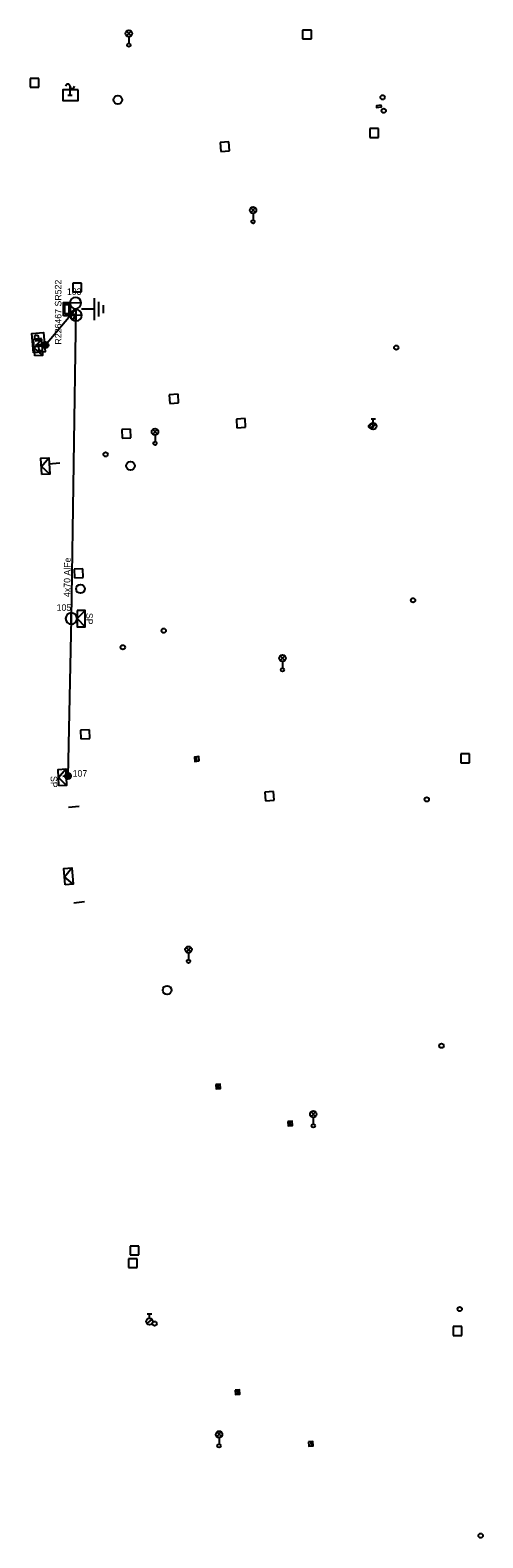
# Model space of a CAD drawing. Extents: x -544660 to -541587, y -1198996 to -1195866.
# Drawn here: x -542658.7 to -542606.9, y -1198470.6 to -1198298.2 of the extents above; entities that cross this region are included whole.
import ezdxf

# ---------------------------------------------------------------- set-up
doc = ezdxf.new("R2010")
doc.units = 0
for name, color, linetype in [('CIZÍ_NADZEM', 7, 'Continuous'), ('ELE_EON', 7, 'Continuous'), ('ELE_EON_POPIS', 7, 'Continuous'), ('SDEL_EON', 7, 'Continuous')]:
    doc.layers.add(name, color=color, linetype=linetype)

msp = doc.modelspace()

# ---------------------------------------------------------------- linework, layer by layer
at = {"layer": 'CIZÍ_NADZEM'}
for p, q in [((-542647.7, -1198298.88), (-542647.18, -1198298.35)), ((-542647.17, -1198298.88), (-542647.7, -1198298.35)), ((-542627.56, -1198298.25), (-542627.56, -1198299.25)), ((-542626.56, -1198298.25), (-542627.56, -1198298.25)), ((-542626.56, -1198299.25), (-542626.56, -1198298.25)), ((-542647.44, -1198298.99), (-542647.44, -1198299.74)), ((-542627.56, -1198299.25), (-542626.56, -1198299.25)), ((-542658.72, -1198303.76), (-542658.72, -1198304.76)), ((-542657.72, -1198303.76), (-542658.72, -1198303.76)), ((-542658.72, -1198304.76), (-542657.72, -1198304.76)), ((-542657.72, -1198304.76), (-542657.72, -1198303.76)), ((-542654.16, -1198305.66), (-542654.16, -1198304.66)), ((-542654.41, -1198305.66), (-542653.91, -1198305.66)), ((-542619.89, -1198309.5), (-542619.89, -1198310.5)), ((-542618.89, -1198309.5), (-542619.89, -1198309.5)), ((-542618.89, -1198310.5), (-542618.89, -1198309.5)), ((-542635.99, -1198311.02), (-542636.99, -1198311.1)), ((-542636.99, -1198311.1), (-542636.91, -1198312.1)), ((-542636.91, -1198312.1), (-542635.91, -1198312.02)), ((-542635.91, -1198312.02), (-542635.99, -1198311.02)), ((-542619.89, -1198310.5), (-542618.89, -1198310.5)), ((-542633.49, -1198319.08), (-542632.97, -1198318.55)), ((-542632.96, -1198319.07), (-542633.49, -1198318.55)), ((-542633.23, -1198319.19), (-542633.23, -1198319.94)), ((-542653.84, -1198327.15), (-542653.84, -1198328.15)), ((-542652.84, -1198327.15), (-542653.84, -1198327.15)), ((-542652.84, -1198328.15), (-542652.84, -1198327.15)), ((-542653.84, -1198328.15), (-542652.84, -1198328.15)), ((-542641.81, -1198339.85), (-542642.81, -1198339.91)), ((-542642.81, -1198339.91), (-542642.75, -1198340.91)), ((-542642.75, -1198340.91), (-542641.75, -1198340.85)), ((-542641.75, -1198340.85), (-542641.81, -1198339.85)), ((-542634.14, -1198342.63), (-542635.14, -1198342.69)), ((-542635.14, -1198342.69), (-542635.08, -1198343.69)), ((-542634.08, -1198343.63), (-542634.14, -1198342.63)), ((-542619.74, -1198342.65), (-542619.24, -1198342.65)), ((-542619.49, -1198343.15), (-542619.49, -1198342.65)), ((-542647.25, -1198343.83), (-542648.25, -1198343.89)), ((-542648.25, -1198343.89), (-542648.19, -1198344.89)), ((-542648.19, -1198344.89), (-542647.19, -1198344.83)), ((-542647.19, -1198344.83), (-542647.25, -1198343.83)), ((-542644.7, -1198344.41), (-542644.18, -1198343.88)), ((-542644.17, -1198344.41), (-542644.7, -1198343.88)), ((-542644.44, -1198344.52), (-542644.44, -1198345.27)), ((-542635.08, -1198343.69), (-542634.08, -1198343.63)), ((-542619.78, -1198343.75), (-542619.19, -1198343.29)), ((-542652.7, -1198359.81), (-542653.7, -1198359.85)), ((-542653.7, -1198359.85), (-542653.66, -1198360.85)), ((-542652.66, -1198360.81), (-542652.7, -1198359.81)), ((-542653.66, -1198360.85), (-542652.66, -1198360.81)), ((-542630.13, -1198370.29), (-542629.61, -1198369.76)), ((-542629.6, -1198370.28), (-542630.13, -1198369.76)), ((-542629.87, -1198370.4), (-542629.87, -1198371.15)), ((-542651.95, -1198378.2), (-542652.95, -1198378.24)), ((-542652.95, -1198378.24), (-542652.91, -1198379.24)), ((-542652.91, -1198379.24), (-542651.91, -1198379.2)), ((-542651.91, -1198379.2), (-542651.95, -1198378.2)), ((-542609.47, -1198380.97), (-542609.47, -1198381.97)), ((-542608.47, -1198380.97), (-542609.47, -1198380.97)), ((-542608.47, -1198381.97), (-542608.47, -1198380.97)), ((-542639.64, -1198381.8), (-542639.68, -1198381.3)), ((-542609.47, -1198381.97), (-542608.47, -1198381.97)), ((-542630.88, -1198385.27), (-542631.88, -1198385.33)), ((-542631.88, -1198385.33), (-542631.82, -1198386.33)), ((-542631.82, -1198386.33), (-542630.82, -1198386.27)), ((-542630.82, -1198386.27), (-542630.88, -1198385.27)), ((-542640.87, -1198403.61), (-542640.35, -1198403.08)), ((-542640.34, -1198403.6), (-542640.87, -1198403.08)), ((-542640.61, -1198403.72), (-542640.61, -1198404.47)), ((-542637.24, -1198418.74), (-542637.2, -1198419.24)), ((-542626.6, -1198422.41), (-542626.08, -1198421.88)), ((-542626.07, -1198422.41), (-542626.6, -1198421.88)), ((-542629.01, -1198422.97), (-542628.97, -1198423.47)), ((-542626.34, -1198422.52), (-542626.34, -1198423.27)), ((-542647.29, -1198437.23), (-542647.29, -1198438.23)), ((-542646.29, -1198437.23), (-542647.29, -1198437.23)), ((-542646.29, -1198438.23), (-542646.29, -1198437.23)), ((-542647.47, -1198438.67), (-542647.47, -1198439.67)), ((-542646.47, -1198438.67), (-542647.47, -1198438.67)), ((-542647.47, -1198439.67), (-542646.47, -1198439.67)), ((-542647.29, -1198438.23), (-542646.29, -1198438.23)), ((-542646.47, -1198439.67), (-542646.47, -1198438.67)), ((-542645.36, -1198446.07), (-542644.77, -1198445.61)), ((-542645.32, -1198444.97), (-542644.82, -1198444.97)), ((-542645.07, -1198445.47), (-542645.07, -1198444.97)), ((-542610.35, -1198446.43), (-542610.35, -1198447.43)), ((-542609.35, -1198446.43), (-542610.35, -1198446.43)), ((-542609.35, -1198447.43), (-542609.35, -1198446.43)), ((-542610.35, -1198447.43), (-542609.35, -1198447.43)), ((-542635.04, -1198453.66), (-542635, -1198454.16)), ((-542637.38, -1198459), (-542636.86, -1198458.47)), ((-542636.85, -1198459), (-542637.38, -1198458.47)), ((-542637.12, -1198459.11), (-542637.12, -1198459.86)), ((-542626.64, -1198459.58), (-542626.6, -1198460.08))]:
    msp.add_line(p, q, dxfattribs=at)
for points in [[(-542653.23, -1198305.08), (-542654.98, -1198305.08), (-542654.98, -1198306.28), (-542653.23, -1198306.28), (-542653.23, -1198305.08)], [(-542618.56, -1198306.81), (-542619.13, -1198306.89), (-542619.1, -1198307.09), (-542618.53, -1198307.01), (-542618.56, -1198306.81)], [(-542654.04, -1198331.25), (-542653.97, -1198330.66), (-542653.67, -1198330.69), (-542653.74, -1198331.29), (-542654.04, -1198331.25)], [(-542658.32, -1198335.11), (-542658.51, -1198332.92), (-542657.2, -1198332.8), (-542657, -1198335), (-542658.32, -1198335.11)], [(-542658.18, -1198333.55), (-542658.2, -1198333.27), (-542658.18, -1198333.17), (-542658.14, -1198333.14), (-542658.07, -1198333.1), (-542657.96, -1198333.09), (-542657.89, -1198333.12), (-542657.85, -1198333.14), (-542657.81, -1198333.23), (-542657.78, -1198333.52)], [(-542657.41, -1198333.49), (-542658.18, -1198333.55)], [(-542658.12, -1198334.21), (-542657.57, -1198334.16), (-542657.47, -1198334.12), (-542657.4, -1198334.05), (-542657.37, -1198333.95), (-542657.38, -1198333.89), (-542657.42, -1198333.8), (-542657.5, -1198333.74), (-542657.61, -1198333.72), (-542658.16, -1198333.77)], [(-542657.34, -1198334.36), (-542658.1, -1198334.43)], [(-542657.7, -1198334.84), (-542657.74, -1198334.4)], [(-542658.06, -1198334.87), (-542657.3, -1198334.8)]]:
    msp.add_lwpolyline(points, dxfattribs=at)
for points in [[(-542639.39, -1198381.77), (-542639.43, -1198381.28), (-542639.93, -1198381.33), (-542639.88, -1198381.82)], [(-542637.49, -1198418.76), (-542637.45, -1198419.26), (-542636.95, -1198419.22), (-542636.99, -1198418.72)], [(-542629.26, -1198422.99), (-542629.22, -1198423.49), (-542628.72, -1198423.45), (-542628.76, -1198422.95)], [(-542635.29, -1198453.68), (-542635.25, -1198454.18), (-542634.75, -1198454.14), (-542634.79, -1198453.64)], [(-542626.89, -1198459.6), (-542626.85, -1198460.1), (-542626.35, -1198460.06), (-542626.39, -1198459.56)]]:
    msp.add_lwpolyline(points, close=True, dxfattribs=at)
for centre, radius in [((-542647.44, -1198298.61), 0.375), ((-542647.44, -1198299.94), 0.2), ((-542648.7, -1198306.2), 0.5), ((-542618.41, -1198305.92), 0.25), ((-542618.28, -1198307.45), 0.25), ((-542633.23, -1198318.81), 0.375), ((-542633.23, -1198320.14), 0.2), ((-542616.85, -1198334.52), 0.25), ((-542619.49, -1198343.52), 0.375), ((-542644.44, -1198344.15), 0.375), ((-542619.74, -1198343.52), 0.25), ((-542650.09, -1198346.73), 0.25), ((-542644.44, -1198345.47), 0.2), ((-542647.24, -1198348.04), 0.5), ((-542652.97, -1198362.11), 0.5), ((-542614.93, -1198363.4), 0.25), ((-542643.44, -1198366.88), 0.25), ((-542648.12, -1198368.78), 0.25), ((-542629.87, -1198370.03), 0.375), ((-542629.87, -1198371.35), 0.2), ((-542613.36, -1198386.16), 0.25), ((-542640.61, -1198403.34), 0.375), ((-542640.61, -1198404.67), 0.2), ((-542643.06, -1198407.96), 0.5), ((-542611.68, -1198414.33), 0.25), ((-542626.34, -1198422.15), 0.375), ((-542626.34, -1198423.47), 0.2), ((-542609.6, -1198444.42), 0.25), ((-542645.07, -1198445.84), 0.375), ((-542644.49, -1198446.08), 0.25), ((-542637.12, -1198458.74), 0.375), ((-542637.12, -1198460.06), 0.2), ((-542607.2, -1198470.32), 0.25)]:
    msp.add_circle(centre, radius, dxfattribs=at)
for centre, start, end in [((-542654.41, -1198304.66), 0, 180), ((-542653.91, -1198304.66), 180, 0)]:
    msp.add_arc(centre, 0.25, start, end, dxfattribs=at)
at = {"layer": 'ELE_EON'}
for p, q in [((-542651.35, -1198331.38), (-542651.35, -1198328.88)), ((-542650.85, -1198330.98), (-542650.85, -1198329.28)), ((-542652.88, -1198329.4), (-542654.18, -1198329.46)), ((-542652.82, -1198330.8), (-542654.12, -1198330.86)), ((-542651.35, -1198330.13), (-542652.85, -1198330.13)), ((-542650.35, -1198330.58), (-542650.35, -1198329.68)), ((-542655.34, -1198347.72), (-542656.58, -1198347.84)), ((-542654.01, -1198366.15), (-542654.01, -1198364.85)), ((-542654.75, -1198383.52), (-542655, -1198383.53)), ((-542654.35, -1198387.05), (-542653.11, -1198386.95)), ((-542653.73, -1198397.97), (-542652.49, -1198397.85))]:
    msp.add_line(p, q, dxfattribs=at)
for points in [[(-542654.9, -1198330.88), (-542654.9, -1198329.38), (-542654.15, -1198329.38), (-542654.15, -1198330.88)], [(-542654.75, -1198330.68), (-542654.75, -1198329.58), (-542654.3, -1198329.58), (-542654.3, -1198330.68)], [(-542658.19, -1198335.48), (-542658.33, -1198333.61), (-542657.43, -1198333.55), (-542657.29, -1198335.41)], [(-542657.38, -1198349.04), (-542657.49, -1198347.17), (-542656.6, -1198347.11), (-542656.48, -1198348.99)], [(-542653.33, -1198364.56), (-542653.33, -1198366.44), (-542652.43, -1198366.44), (-542652.43, -1198364.56)], [(-542655.45, -1198384.6), (-542655.52, -1198382.73), (-542654.63, -1198382.69), (-542654.55, -1198384.57)], [(-542654.71, -1198395.93), (-542654.85, -1198394.06), (-542653.95, -1198394), (-542653.81, -1198395.86)]]:
    msp.add_lwpolyline(points, close=True, dxfattribs=at)
for points in [[(-542653.5, -1198330.13), (-542656.98, -1198334.23)], [(-542653.5, -1198330.13), (-542654.01, -1198365.5), (-542654.4, -1198383.5)], [(-542657.29, -1198335.41), (-542658.26, -1198334.55), (-542657.43, -1198333.55)], [(-542656.48, -1198348.99), (-542657.44, -1198348.1), (-542656.6, -1198347.11)], [(-542652.43, -1198364.56), (-542653.33, -1198365.5), (-542652.43, -1198366.44)], [(-542654.55, -1198384.57), (-542655.49, -1198383.66), (-542654.63, -1198382.69)], [(-542653.81, -1198395.86), (-542654.78, -1198395), (-542653.95, -1198394)]]:
    msp.add_lwpolyline(points, dxfattribs=at)
for radius in [0.35, 0.175]:
    msp.add_circle((-542654.4, -1198383.5), radius, dxfattribs=at)
for centre, start, end in [((-542653.53, -1198329.43), 2.7668, 182.7668), ((-542653.53, -1198329.43), 182.7668, 2.7668), ((-542653.47, -1198330.83), 2.7668, 182.7668), ((-542653.47, -1198330.83), 182.7668, 2.7668), ((-542654.01, -1198365.5), 90, 270), ((-542654.01, -1198365.5), 270, 90)]:
    msp.add_arc(centre, 0.65, start, end, dxfattribs=at)
at = {"layer": 'SDEL_EON'}
msp.add_line((-542657.33, -1198334.23), (-542657.58, -1198334.23), dxfattribs=at)
for radius in [0.35, 0.175]:
    msp.add_circle((-542656.98, -1198334.23), radius, dxfattribs=at)

# ---------------------------------------------------------------- texts
at = {"layer": 'ELE_EON_POPIS'}
for s, rotation, p in [('R226467 SR522', 90, (-542655.14, -1198334.18)), ('4x70 AlFe', 89.1739, (-542654.14, -1198363.04)), ('SP', 270, (-542652.31, -1198364.85)), ('SP', 272.1476, (-542656.39, -1198383.5))]:
    msp.add_text(s, height=0.75, rotation=rotation, dxfattribs=at).set_placement(p)
for s, p in [('103', (-542654.52, -1198328.5)), ('105', (-542655.69, -1198364.61)), ('107', (-542653.86, -1198383.57))]:
    msp.add_text(s, height=0.75, dxfattribs=at).set_placement(p)

doc.saveas('drawing.dxf')
